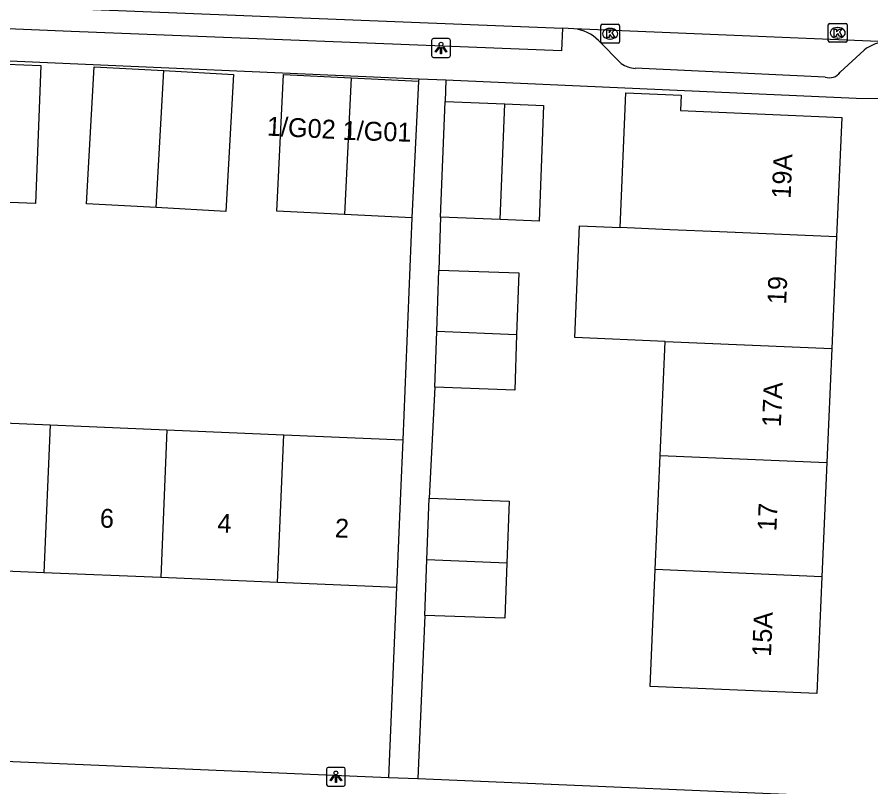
# Model space of a CAD drawing. Extents: x 160732 to 162105, y 387428 to 388479.
# Drawn here: x 161205.54 to 161250.8, y 387576.48 to 387617.29 of the extents above; entities that cross this region are included whole.
import ezdxf

# ---------------------------------------------------------------- set-up
doc = ezdxf.new("R2010")
doc.units = 0
for name, color, linetype in [('IMGEO_Erf', 7, 'Continuous'), ('IMGEO_Kolk', 7, 'Continuous'), ('IMGEO_Lichtpunt', 7, 'Continuous'), ('IMGEO_Pand', 7, 'Continuous'), ('IMGEO_Pand_nummerreeks', 7, 'Continuous'), ('IMGEO_Rijbaan_lokaal_open', 7, 'Continuous'), ('IMGEO_Voetpad_open', 7, 'Continuous')]:
    doc.layers.add(name, color=color, linetype=linetype)

msp = doc.modelspace()

# ---------------------------------------------------------------- linework, layer by layer
at = {"layer": 'IMGEO_Erf'}
msp.add_lwpolyline([(161231.39, 387612.687), (161233.449, 387612.607), (161233.21, 387606.474), (161231.151, 387606.554)], dxfattribs=at)
at = {"layer": 'IMGEO_Kolk'}
for p, q in [((161236.549, 387616.908), (161237.401, 387616.908)), ((161248.537, 387616.03), (161248.537, 387616.882)), ((161248.612, 387616.956), (161249.464, 387616.956)), ((161249.538, 387616.882), (161249.538, 387616.03)), ((161236.474, 387615.982), (161236.474, 387616.834)), ((161236.962, 387616.688), (161236.987, 387616.688)), ((161237.475, 387616.834), (161237.475, 387615.982)), ((161249.025, 387616.736), (161249.05, 387616.736)), ((161236.985, 387616.128), (161236.96, 387616.128)), ((161249.048, 387616.176), (161249.023, 387616.176)), ((161237.401, 387615.908), (161236.549, 387615.908)), ((161249.464, 387615.956), (161248.612, 387615.956))]:
    msp.add_line(p, q, dxfattribs=at)
for points in [[(161236.549, 387616.908), (161237.401, 387616.908)], [(161248.537, 387616.03), (161248.537, 387616.882)], [(161248.612, 387616.956), (161249.464, 387616.956)], [(161249.538, 387616.882), (161249.538, 387616.03)], [(161236.474, 387615.982), (161236.474, 387616.834)], [(161236.795, 387616.608), (161236.918, 387616.608), (161236.918, 387616.457), (161237.048, 387616.608), (161237.212, 387616.608), (161237.066, 387616.457), (161237.219, 387616.208), (161237.067, 387616.208), (161236.982, 387616.372), (161236.918, 387616.305), (161236.918, 387616.208), (161236.795, 387616.208), (161236.795, 387616.608)], [(161237.475, 387616.834), (161237.475, 387615.982)], [(161248.858, 387616.656), (161248.981, 387616.656), (161248.981, 387616.505), (161249.111, 387616.656), (161249.275, 387616.656), (161249.129, 387616.505), (161249.282, 387616.256), (161249.13, 387616.256), (161249.045, 387616.42), (161248.981, 387616.353), (161248.981, 387616.256), (161248.858, 387616.256), (161248.858, 387616.656)], [(161237.401, 387615.908), (161236.549, 387615.908)], [(161249.464, 387615.956), (161248.612, 387615.956)]]:
    msp.add_lwpolyline(points, dxfattribs=at)
for centre, start, end in [((161236.551, 387616.832), 91.552, 178.448), ((161236.551, 387616.832), 91.552, 178.448), ((161237.399, 387616.832), 1.552, 88.448), ((161237.399, 387616.832), 1.552, 88.448), ((161248.614, 387616.88), 91.552, 178.448), ((161248.614, 387616.88), 91.552, 178.448), ((161249.462, 387616.88), 1.552, 88.448), ((161249.462, 387616.88), 1.552, 88.448), ((161236.551, 387615.984), 181.552, 268.448), ((161236.551, 387615.984), 181.552, 268.448), ((161237.399, 387615.984), 271.552, 358.448), ((161237.399, 387615.984), 271.552, 358.448), ((161248.614, 387616.032), 181.552, 268.448), ((161248.614, 387616.032), 181.552, 268.448), ((161249.462, 387616.032), 271.552, 358.448), ((161249.462, 387616.032), 271.552, 358.448)]:
    msp.add_arc(centre, 0.0765, start, end, dxfattribs=at)
for centre, major_axis, ratio, start_param, end_param in [((161236.961, 387616.408), (-0.387, 0.002), 0.722429, 4.712389, 7.853982), ((161236.986, 387616.408), (-0.39, 0.002), 0.717154, 1.570796, 4.712389), ((161249.024, 387616.456), (-0.387, 0.002), 0.722429, 4.712389, 7.853982), ((161249.049, 387616.456), (-0.39, 0.002), 0.717154, 1.570796, 4.712389)]:
    msp.add_ellipse(centre, major_axis=major_axis, ratio=ratio, start_param=start_param, end_param=end_param, dxfattribs=at)
at = {"layer": 'IMGEO_Lichtpunt'}
for p, q in [((161227.514, 387616.056), (161227.514, 387615.249)), ((161227.514, 387616.056), (161227.514, 387615.249)), ((161228.416, 387616.151), (161227.608, 387616.151)), ((161228.416, 387616.151), (161227.608, 387616.151)), ((161228.51, 387615.249), (161228.51, 387616.056)), ((161228.51, 387615.249), (161228.51, 387616.056)), ((161227.608, 387615.155), (161228.416, 387615.155)), ((161227.608, 387615.155), (161228.416, 387615.155)), ((161222.844, 387577.518), (161222.036, 387577.518)), ((161222.844, 387577.518), (161222.036, 387577.518)), ((161221.942, 387577.423), (161221.942, 387576.616)), ((161221.942, 387577.423), (161221.942, 387576.616)), ((161222.938, 387576.616), (161222.938, 387577.423)), ((161222.938, 387576.616), (161222.938, 387577.423)), ((161222.036, 387576.522), (161222.844, 387576.522)), ((161222.036, 387576.522), (161222.844, 387576.522))]:
    msp.add_line(p, q, dxfattribs=at)
for points in [[(161227.888, 387615.72), (161227.927, 387615.692), (161227.739, 387615.43), (161227.701, 387615.457), (161227.888, 387615.72)], [(161227.99, 387615.672), (161228.037, 387615.672), (161228.037, 387615.35), (161227.99, 387615.35), (161227.99, 387615.672)], [(161228.1, 387615.692), (161228.138, 387615.719), (161228.325, 387615.457), (161228.286, 387615.429), (161228.1, 387615.692)], [(161222.316, 387577.087), (161222.355, 387577.059), (161222.167, 387576.797), (161222.129, 387576.824), (161222.316, 387577.087)], [(161222.418, 387577.039), (161222.465, 387577.039), (161222.465, 387576.717), (161222.418, 387576.717), (161222.418, 387577.039)], [(161222.528, 387577.059), (161222.566, 387577.086), (161222.753, 387576.824), (161222.714, 387576.796), (161222.528, 387577.059)]]:
    msp.add_lwpolyline(points, dxfattribs=at)
for centre in [(161228.013, 387615.854), (161222.441, 387577.221)]:
    msp.add_circle(centre, 0.0994, dxfattribs=at)
for centre, start, end in [((161227.608, 387616.056), 90, 180), ((161227.608, 387616.056), 90, 180), ((161228.416, 387616.056), 0, 90), ((161228.416, 387616.056), 0, 90), ((161227.608, 387615.249), 180, 270), ((161227.608, 387615.249), 180, 270), ((161228.416, 387615.249), 270, 0), ((161228.416, 387615.249), 270, 360), ((161222.036, 387577.423), 90, 180), ((161222.036, 387577.423), 90, 180), ((161222.844, 387577.423), 0, 90), ((161222.844, 387577.423), 0, 90), ((161222.036, 387576.616), 180, 270), ((161222.036, 387576.616), 180, 270), ((161222.844, 387576.616), 270, 0), ((161222.844, 387576.616), 270, 360)]:
    msp.add_arc(centre, 0.0946, start, end, dxfattribs=at)
at = {"layer": 'IMGEO_Pand'}
for points in [[(161203.169, 387614.872), (161206.807, 387614.729), (161206.52, 387607.407), (161202.882, 387607.55)], [(161212.914, 387607.189), (161209.221, 387607.396), (161209.629, 387614.662), (161213.322, 387614.455)], [(161212.914, 387607.189), (161213.322, 387614.455)], [(161213.322, 387614.455), (161217.016, 387614.247), (161216.608, 387606.981), (161212.914, 387607.189)], [(161222.887, 387606.832), (161219.311, 387607.008), (161219.669, 387614.25), (161223.245, 387614.073)], [(161223.245, 387614.073), (161222.887, 387606.832)], [(161223.245, 387614.073), (161226.821, 387613.896)], [(161226.821, 387613.896), (161226.463, 387606.655)], [(161237.508, 387606.13), (161237.815, 387613.273), (161240.742, 387613.146), (161240.707, 387612.336), (161249.249, 387611.969), (161248.977, 387605.633)], [(161227.989, 387606.677), (161228.228, 387612.81)], [(161228.228, 387612.81), (161231.39, 387612.687)], [(161231.151, 387606.554), (161231.39, 387612.687)], [(161226.463, 387606.655), (161222.887, 387606.832)], [(161231.151, 387606.554), (161227.989, 387606.677)], [(161239.888, 387600.101), (161235.102, 387600.306), (161235.356, 387606.23), (161237.508, 387606.13)], [(161248.977, 387605.633), (161242.777, 387605.898), (161240.142, 387606.017), (161237.508, 387606.13)], [(161248.977, 387605.633), (161248.723, 387599.722)], [(161227.781, 387600.62), (161227.896, 387603.879)], [(161227.896, 387603.879), (161232.135, 387603.73), (161232.019, 387600.439)], [(161227.677, 387597.669), (161227.781, 387600.62)], [(161232.019, 387600.439), (161227.781, 387600.62)], [(161232.019, 387600.439), (161231.916, 387597.52), (161227.677, 387597.669)], [(161239.629, 387594.051), (161239.888, 387600.101)], [(161239.888, 387600.101), (161248.723, 387599.722)], [(161248.723, 387599.722), (161248.464, 387593.672)], [(161201.105, 387595.934), (161207.295, 387595.673)], [(161207.295, 387595.673), (161206.965, 387587.838)], [(161207.295, 387595.673), (161213.485, 387595.412)], [(161213.485, 387595.412), (161213.155, 387587.577)], [(161213.485, 387595.412), (161219.675, 387595.152)], [(161219.345, 387587.317), (161219.675, 387595.152)], [(161219.675, 387595.152), (161225.985, 387594.886)], [(161225.985, 387594.886), (161225.865, 387592.047), (161225.655, 387587.051)], [(161239.369, 387588.002), (161239.629, 387594.051)], [(161239.629, 387594.051), (161248.464, 387593.672)], [(161248.464, 387593.672), (161248.204, 387587.623)], [(161227.262, 387588.521), (161227.377, 387591.78)], [(161227.377, 387591.78), (161231.616, 387591.631), (161231.5, 387588.34)], [(161227.158, 387585.57), (161227.262, 387588.521)], [(161231.5, 387588.34), (161227.262, 387588.521)], [(161206.965, 387587.838), (161200.775, 387588.098)], [(161231.5, 387588.34), (161231.397, 387585.421), (161227.158, 387585.57)], [(161248.204, 387587.623), (161247.938, 387581.425), (161239.103, 387581.804), (161239.369, 387588.002)], [(161248.204, 387587.623), (161239.369, 387588.002)], [(161213.155, 387587.577), (161206.965, 387587.838)], [(161219.345, 387587.317), (161213.155, 387587.577)], [(161225.655, 387587.051), (161219.345, 387587.317)]]:
    msp.add_lwpolyline(points, dxfattribs=at)
at = {"layer": 'IMGEO_Rijbaan_lokaal_open'}
for points in [[(161189.538, 387618.499), (161234.447, 387616.696)], [(161235.056, 387616.672), (161234.447, 387616.696)], [(161251.616, 387615.972), (161235.056, 387616.672)]]:
    msp.add_lwpolyline(points, dxfattribs=at)
at = {"layer": 'IMGEO_Voetpad_open'}
for points in [[(161234.447, 387616.696), (161234.394, 387615.505), (161208.407, 387616.534), (161189.465, 387617.313), (161189.538, 387618.499)], [(161237.566, 387614.826), (161236.361, 387616.047)], [(161189.469, 387615.669), (161226.827, 387614.021)], [(161250.437, 387615.54), (161249.162, 387614.371)], [(161248.375, 387614.111), (161238.306, 387614.574)], [(161226.827, 387614.021), (161226.821, 387613.896)], [(161226.827, 387614.021), (161228.273, 387613.957)], [(161228.273, 387613.957), (161228.228, 387612.81)], [(161228.273, 387613.957), (161250.02, 387612.998), (161253.586, 387612.955)], [(161226.463, 387606.655), (161225.985, 387594.886)], [(161227.989, 387606.677), (161227.896, 387603.879)], [(161227.677, 387597.669), (161227.377, 387591.78)], [(161225.655, 387587.051), (161225.228, 387576.988)], [(161227.158, 387585.57), (161226.791, 387576.922)], [(161187.85, 387578.575), (161225.228, 387576.988)], [(161225.228, 387576.988), (161226.791, 387576.922)], [(161226.791, 387576.922), (161251.719, 387575.864)]]:
    msp.add_lwpolyline(points, dxfattribs=at)
for centre, radius, start, end in [((161234.86, 387614.589), 2.093, 44.1822, 84.6357), ((161251.671, 387613.996), 1.977, 91.6048, 128.6421), ((161238.367, 387615.965), 1.393, 234.8952, 267.4933), ((161248.6, 387614.751), 0.679, 250.6531, 325.9107)]:
    msp.add_arc(centre, radius, start, end, dxfattribs=at)

# ---------------------------------------------------------------- texts
at = {"layer": 'IMGEO_Pand_nummerreeks'}
for s, rotation, p in [('1/G02', 357.1664, (161218.765, 387611.011)), ('1/G01', 358.3397, (161222.788, 387610.786)), ('19A', 87.5423, (161246.541, 387607.645)), ('19', 87.5422, (161246.302, 387602.051)), ('17A', 87.5423, (161246.021, 387595.542)), ('6', 357.5902, (161209.912, 387590.236)), ('17', 87.5423, (161245.786, 387590.021)), ('4', 357.5902, (161216.141, 387589.974)), ('2', 357.5902, (161222.369, 387589.712)), ('15A', 87.5423, (161245.499, 387583.368))]:
    msp.add_text(s, height=1, rotation=rotation, dxfattribs=at).set_placement(p)

doc.saveas('drawing.dxf')
